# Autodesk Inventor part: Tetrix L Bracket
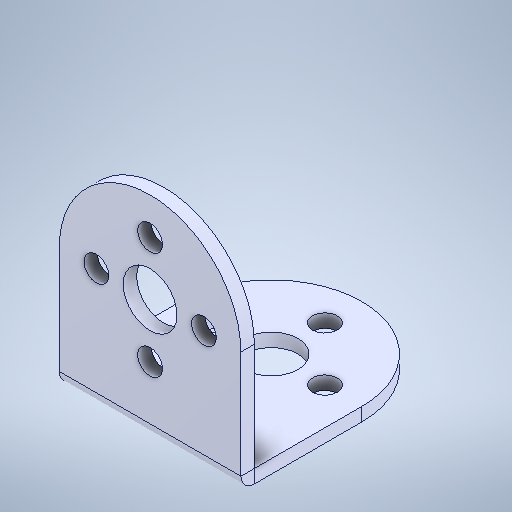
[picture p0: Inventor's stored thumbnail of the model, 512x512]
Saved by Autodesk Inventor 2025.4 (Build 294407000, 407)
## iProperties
Created: 2021-10
Part Number: Tetrix L Bracket
Material: Genérico
Document SubType Name: Modeling
Designer: usuario
Density: 1 g/cm^3
Appearance: Valor por defecto
Author: usuario
Sending System: SolidWorks 2016
Last Author: LENOVO
Last Saved: 2021-10-21
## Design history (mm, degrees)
feature "Edge-Flange1"
node "Plane1"
node "Sólido1"
